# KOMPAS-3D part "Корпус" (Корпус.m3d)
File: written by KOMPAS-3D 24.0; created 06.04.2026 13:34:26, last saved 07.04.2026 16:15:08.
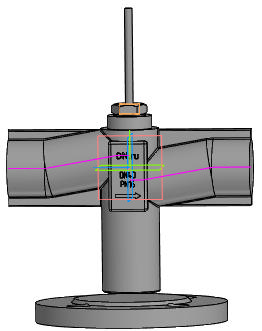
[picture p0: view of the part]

Document properties: Автор: R2D2; Полное имя файла: E:\Работа\Зайцев\Солянка\VSR1-13V-PED-F Клапан запорно-регулирующий DN.ru\DN40\исходные материалы\Корпус.m3d

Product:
- Body: Труба / Нестандартная труба / L = 95.8 мм  | qty 1
    Материал: Нестандартная труба (density 7856 kg/m3)
    Масса: 3.797101
    Раздел спецификации: Детали
    Примечание: 1,2 кг
    additional columns: Pipeline; 0.045; 0; 0; 0.002; 0.09584; true; 0.04
- Body: Труба / Нестандартная труба / L = 95.8 мм  | qty 1
    Материал: Нестандартная труба (density 7856 kg/m3)
    Масса: 3.797101
    Раздел спецификации: Детали
    Форматы листов документа: БЧ
    Примечание: 1,2 кг
    additional columns: Pipeline; 0.045; 0; 0; 0.002; 0.09584; true; 0.04
- Component [standard]: Гайка М16-6H ГОСТ 5916-70  | qty 1  | Масса: 0.01768; Рассекать на разрезах: no; source file: C:\Program Files\ASCON\KOMPAS-3D v24\Libs\PolynomLib\DATA\vault\Methods\Kompas\3D\PLib_Nut_OST92_900.m3d
- Component [standard]: (unnamed)  | qty 1  | Материал: ВЧ40 ГОСТ 7293-85 (density 7200 kg/m3); Масса: 1.939072; Рассекать на разрезах: no; additional columns: 40-16-B-2-ВЧ40-II; Заглушка; ГОСТ 34785-2021
- Body: Тело 4  | qty 1
    Материал: Нестандартная труба (density 7856 kg/m3)
    Масса: 3.797101
- Part/product: Корпус
    Масса: 6.9

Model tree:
1. Эскиз:1
2. Труба:1  (labels: {F703FF30-5BE6-4673-A7F1-8EDA1BE1E2D1}; SHAPEOBJECT3D_ATTR_BUTT; SHAPEOBJECT3D_ATTR_VALID; SHAPEOBJECT3D_ATTR_BUTT_AREA)
     PIPE_R = 7
3. Труба:2  (labels: {F703FF30-5BE6-4673-A7F1-8EDA1BE1E2D1}; SHAPEOBJECT3D_ATTR_BUTT; SHAPEOBJECT3D_ATTR_VALID; SHAPEOBJECT3D_ATTR_BUTT_AREA)
     PIPE_R = 7
4. Эскиз:2
5. Элемент выдавливания:1
     Расстояние 1 = 41; Смещение 1 = -1; Расстояние 2 = 97; Смещение 2 = -5
6. РЕБРО  (with: Ребро.Труба:2)
7. Элемент выдавливания:2
     Расстояние 1 = 6
8. Эскиз:4  (with: Грань.Элемент выдавливания:1)
9. Скругление:3  (with: Ребро.Элемент выдавливания:2)
10. Элемент выдавливания:3
     Расстояние 1 = 1
11. Эскиз:5  (with: Грань.Элемент выдавливания:3)
12. Элемент выдавливания:4
     Расстояние 1 = 7.5; Смещение 1 = 0.5
13. ШТОК
14. Элемент выдавливания:5
15. ОТЛИВКА
16. Скругление:6  (with: Грань.Элемент выдавливания:1)
17. Элемент выдавливания:6  (with: Грань.Элемент выдавливания:1)
     Смещение 1 = 4
18. Эскиз:8  (with: Грань.Элемент выдавливания:6)
19. Элемент выдавливания:7
     Расстояние 1 = 0.5
20. Скругление:7  (with: Ребро.Элемент выдавливания:6)
     Радиус = 2
21. Эскиз:9  (with: Грань.Элемент выдавливания:1, Ребро.Скругление:6, Ребро.Элемент выдавливания:5)
22. Элемент вращения:1  (with: Грань.Элемент выдавливания:3)
     Угол 1 = 360

Expressions: DS/2+3
Referenced files in C:\Program Files\ASCON\KOMPAS-3D v24\Libs\Pipeline\: StylesTemplate.a3d, TemplateHPH, InsulationStylesTemplate.a3d, Insulation
Referenced files in C:\Program Files\ASCON\KOMPAS-3D v24\Templates\: Констр. чертеж А3 гориз. перв. лист.cdt
Referenced files in E:\Работа\Зайцев\Солянка\VSR1-13V-PED-F Клапан запорно-регулирующий DN.ru\DN15\DN15 Kv0.16\исходные материалы\: 
Referenced files in C:\Program Files\ASCON\KOMPAS-3D v24\Libs\PolynomLib\DATA\vault\Methods\Kompas\3D\: PLib_Nut_OST92_900.m3d, PLib_Flange_Blind_GOST_34785_2100.m3d
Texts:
  Отводы ГОСТ 17375-2001
  Констр. чертеж А3 гориз. перв. лист.cdt
  BOSimple***PART:2c8e7818-1586-f79e-db7d-bc045ba468e4***SHORTLOC:Root±30±10±20±©{}110±10±50±80[Нет;Без покрытия;Без указания материала;-;16;2;24]
  BOSimple***Material:38d6725a-5efe-48e1-b177-a7817acb862a
  BOSimple***PART:9700d21d-e1f1-d8a0-5acd-0feb68792fa4***SHORTLOC:B619_EF039B503CC34112[2;16;40;Круглая;II;ВЧ40 ГОСТ 7293-85]
  var3D
  GOST 2.304 type A
  PN16
  LL-10
  DN+5
  bcut1
  hole1
  hcut1
  hole2
  cut1
  Труба / Нестандартная труба / L = %s мм
  Plane. Начало координат
  Ось Y.Начало координат
  Плоскость ZX.Начало координат
  Плоскость ZY.Начало координат
  Горизонтальная плоскость. Начало координат
  Плоскость XY.Начало координат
